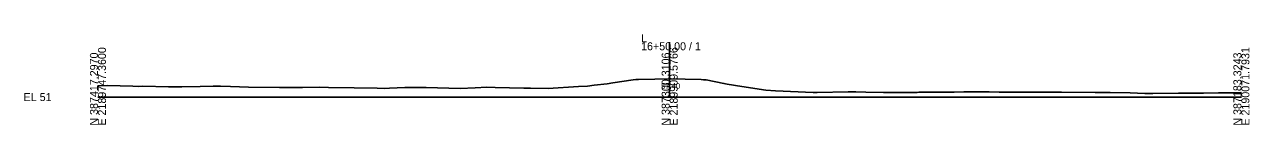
# Model space of a CAD drawing. Extents: x -26 to 2190750, y -10 to 388496.
# Drawn here: x -25.7 to 402.8, y 490.3 to 522 of the extents above; entities that cross this region are included whole.
import ezdxf

# ---------------------------------------------------------------- set-up
doc = ezdxf.new("R2010")
doc.units = 0
for name, color, linetype in [('Default', 7, 'Continuous'), ('Exist Cross Section Cell', 7, 'Continuous'), ('Exist XS Center Line Elevation Label', 7, 'Continuous'), ('Exist XS Ground Line', 7, 'Continuous')]:
    doc.layers.add(name, color=color, linetype=linetype)

msp = doc.modelspace()

# ---------------------------------------------------------------- linework, layer by layer
at = {"layer": 'Exist Cross Section Cell'}
for p, q in [((200, 500), (200, 519.2)), ((0, 500), (200, 500)), ((200, 500), (400, 500))]:
    msp.add_line(p, q, dxfattribs=at)
at = {"layer": 'Exist XS Ground Line'}
msp.add_lwpolyline([(0, 503.96), (3.36, 504), (12.23, 503.77), (14.24, 503.74), (15.69, 503.78), (24.64, 503.62), (28.02, 503.58), (29.33, 503.58), (35.73, 503.68), (40.35, 503.8), (42.89, 503.79), (46.42, 503.71), (52.68, 503.45), (63.52, 503.38), (65.01, 503.4), (71.55, 503.39), (77.34, 503.45), (80.62, 503.4), (89.67, 503.25), (97.72, 503.11), (100.21, 503.03), (102, 503.11), (107.37, 503.31), (114.82, 503.4), (126.66, 503.04), (131.91, 503.24), (136.03, 503.47), (138.99, 503.32), (149.01, 503.16), (150.35, 503.16), (151.32, 503.16), (157.52, 502.99), (168.07, 503.68), (171.29, 503.86), (173.63, 504.12), (178.1, 504.6), (180.15, 504.93), (187.27, 506.07), (188.14, 506.1), (189.06, 506.12), (194.76, 506.27), (200.02, 506.4), (205.47, 506.26), (211, 506.1), (211.88, 506.07), (212.73, 506.02), (218.99, 504.79), (220.17, 504.53), (225.28, 503.76), (233.59, 502.45), (236.98, 502.22), (250.16, 501.56), (251.57, 501.57), (262.49, 501.81), (265.08, 501.85), (268.67, 501.75), (274.82, 501.59), (279.41, 501.57), (285.76, 501.62), (286.57, 501.64), (287.15, 501.66), (290.74, 501.66), (299.48, 501.74), (302.86, 501.8), (311.81, 501.83), (315.22, 501.7), (319.96, 501.72), (324.14, 501.76), (334.96, 501.77), (336.47, 501.77), (337.06, 501.77), (348.8, 501.57), (354.15, 501.56), (361.13, 501.5), (366.25, 501.28), (368.99, 501.29), (378.06, 501.4), (381.63, 501.4), (386.74, 501.41), (391.97, 501.44), (398.39, 501.45), (400, 501.45)], dxfattribs=at)

# ---------------------------------------------------------------- texts
at = {"layer": 'Default'}
msp.add_text('-', height=0.0001, dxfattribs=at).set_placement((0, 500))
at = {"layer": 'Exist Cross Section Cell'}
for s, p in [('16+50.00 / 1', (190, 516.4)), ('L', (190, 519.2)), ('EL 51', (-26, 498.6))]:
    msp.add_text(s, height=2.8, dxfattribs=at).set_placement(p)
for s, p in [('N 387417.2970', (0, 490)), ('E 2189747.3600', (2.8, 490)), ('N 387300.3106', (200, 490)), ('E 2189909.5766', (202.8, 490)), ('N 387183.3243', (400, 490)), ('E 2190071.7931', (402.8, 490))]:
    msp.add_text(s, height=2.8, rotation=90, dxfattribs=at).set_placement(p)
at = {"layer": 'Exist XS Center Line Elevation Label'}
msp.add_text('57.40', height=2, dxfattribs=at).set_placement((196.98, 502.88))

doc.saveas('drawing.dxf')
